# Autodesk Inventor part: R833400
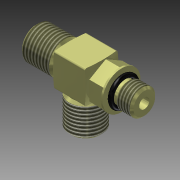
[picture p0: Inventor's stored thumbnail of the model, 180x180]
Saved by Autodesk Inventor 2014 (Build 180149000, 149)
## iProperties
Shininess: 20.0
Length Units: 11272
Angle Units: 11279
Time Units: 11290
Mass Units: 11286
Length Display Precision: 3
Angle Display Precision: 2
Company: Autodesk, Inc.
Created: 2002-06
Part Number: R833400
Material: Steel, Mild A-36
Description: Fitting; TE-C9GC94-S
Document SubType Name: Modeling
Designer: Autodesk, Inc.
Density: 1 g/cm^3
Appearance: Yellow Zinc
Density: 0.0
Volumn: 0.0
Area: 0.0
PropertySet Name: Model Information
Control State: 0
Master: False
Checked Out: False
Last Check In By: JT
Last Check In Date: 2003-06-20
Title: Fitting; TE-C9GC94-S
Author: Autodesk, Inc.
Comments: -
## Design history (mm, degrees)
sketch "Sketch1"
  geometry: L1 (-7.137, -7.137)-(7.137, -7.137); L2 (7.137, -7.137)-(7.137, 7.137); L3 (7.137, 7.137)-(-7.137, 7.137); L4 (-7.137, 7.137)-(-7.137, -7.137); L5 (-7.137, -7.137)-(7.137, 7.137); 2 further points
  constraints: 10 end point, 2 parallel, 1 coincident, 1 horizontal, 1 midpoint, 1 perpendicular
  dimensions: "d3" = 14.2748 distance of L2.end L3.end (= Body_Size); "d4" = 14.2748 distance of L3.end L1.start (= Body_Size)
extrude "Extrusion2" new body sketch "Sketch1" stored distance "d5" = 14.2748 (= Body_Size); taper "d6" = 0 deg
workplane "Work Plane1"
sketch "Sketch2"
  geometry: L1 (-7.137, 10.094)-(-7.137, 0) reference; L2 (7.137, 0)-(7.137, 10.094) reference; L3 (-7.137, 7.137)-(-6.616, 10.094); L4 (7.137, 7.137)-(6.616, 10.094); L5 (7.137, 7.137)-(-7.137, 7.137); L6 (-9.992, 0)-(9.992, 0) reference; L7 (-7.137, 10.094)-(-6.616, 10.094); L8 (6.616, 10.094)-(7.137, 10.094)
  constraints: 10 end point, 2 parallel, 2 point on line, 1 horizontal
  dimensions: "d7" = 14.2748 diameter of L5 L6 (= Body_Size); "d8" = 10 deg angle of L3 L1; "d9" = 10 deg angle of L2 L4 (= d8)
revolve "Revolution1" sketch "Sketch2" stored, may be unused: angle "d10" = 90 deg
fillet "Fillet1" dims "d11" = 0.762
sketch "Sketch3"
  geometry: L1 (-7.137, 7.137)-(-7.137, 0) reference; L2 (-7.137, 0)-(-7.137, -7.137) reference; L3 (0, 0)-(-46.922, 0); L4 (0, 0)-(49.071, 0); L5 (0, 0)-(0, -39.416); L6 (6.708, -7.137)-(-6.708, -7.137) reference; L7 (7.137, 0)-(7.137, 7.137) reference; L8 (7.137, -7.137)-(7.137, 0) reference; L9 (-7.137, 6.134)-(-7.899, 6.134); L10 (-7.899, 6.134)-(-8.909, 7.144); L11 (-8.909, 7.144)-(-20.58, 7.144); L12 (-20.58, 7.144)-(-21.59, 6.134); L13 (-21.59, 6.134)-(-21.59, 5.499); L14 (-21.59, 5.499)-(-20.244, 5.499); L15 (-20.244, 5.499)-(-20.244, 3.086); L16 (-20.244, 3.086)-(-21.59, 3.086); L17 (-21.59, 3.086)-(-21.59, 2.184); L18 (-21.59, 2.184)-(-7.137, 2.184); L19 (7.137, 6.134)-(7.899, 6.134); L20 (7.899, 6.134)-(8.909, 7.144); L21 (8.909, 7.144)-(20.58, 7.144); L22 (20.58, 7.144)-(21.59, 6.134); L23 (21.59, 6.134)-(21.59, 5.499); L24 (21.59, 5.499)-(20.244, 5.499); L25 (20.244, 5.499)-(20.244, 3.086); L26 (20.244, 3.086)-(21.59, 3.086); L27 (21.59, 3.086)-(21.59, 2.184); L28 (21.59, 2.184)-(7.137, 2.184); L29 (-6.134, -7.137)-(-6.134, -7.899); L30 (-6.134, -7.899)-(-7.144, -8.909); L31 (-7.144, -8.909)-(-7.144, -20.58); L32 (-7.144, -20.58)-(-6.134, -21.59); L33 (-6.134, -21.59)-(-5.499, -21.59); L34 (-5.499, -21.59)-(-5.499, -20.244); L35 (-5.499, -20.244)-(-3.086, -20.244); L36 (-3.086, -20.244)-(-3.086, -21.59); L37 (-3.086, -21.59)-(-2.184, -21.59); L38 (-2.184, -21.59)-(-2.184, -7.137); C1 r 0.787 at (-21.031, 4.61); C2 r 0.787 at (-4.61, -21.031); C3 r 0.787 at (21.031, 4.61)
  constraints: 66 end point, 14 perpendicular, 13 parallel, 6 point on line, 5 collinear, 3 centre point, 2 horizontal alignment, 1 vertical alignment
  dimensions: "d12" = 14.2875 diameter of L11 L3 (= Male2_Face_Seal_Thread_OD); "d13" = 12.2682 diameter of L12.end L3 (= Male2_Face_Seal_Lip); "d14" = 45 deg angle of L11 L12; "d15" = 10.9982 diameter of L14 L3 (= Male2_Face_Seal_Groove_Dia); "d16" = 1.3462 distance from line of L15.end L13; "d17" = 4.3688 diameter of L18 L3 (= Male2_Face_Seal_ID); "d18" = 2.413 distance between parallel lines of L16 L14; "d19" = 21.59 distance from line of L13 L3.start (= Male1_M); "d20" = 0.762 distance of L9.start L9.end (= Male2_Face_Seal_Undercut_Length_H); "d21" = 21.59 distance from line of L33 L3.start (= Male1_M); "d22" = 14.2875 diameter of L31 L5 (= Male2_Face_Seal_Thread_OD); "d23" = 45 deg angle of L31 L32; "d24" = 12.2682 diameter of L32.end L5 (= Male2_Face_Seal_Lip); "d25" = 0.762 distance of L29.start L29.end (= Male2_Face_Seal_Undercut_Length_H); "d26" = 10.9982 diameter of L34 L5 (= Male2_Face_Seal_Groove_Dia); "d27" = 2.413 distance between parallel lines of L36 L34; "d28" = 1.3462 distance between parallel lines of L35 L37; "d29" = 4.3688 diameter of L38 L5 (= Male2_Face_Seal_ID); "d30" = 21.59 distance from line of L27 L3.start (= Male2_M); "d31" = 14.2875 diameter of L21 L4 (= Male1_Face_Seal_Thread_OD); "d32" = 10.9982 diameter of L24 L4 (= Male1_Face_Seal_Groove_Dia); "d33" = 2.413 distance between parallel lines of L26 L24; "d34" = 1.3462 distance between parallel lines of L27 L25; "d35" = 0.762 distance of L19.start L19.end (= Male1_Face_Seal_Undercut_Length_H); "d36" = 45 deg angle of L21 L22; "d37" = 12.2682 diameter of L22.end L4 (= Male1_Face_Seal_Lip); "d38" = 4.3688 diameter of L28 L4 (= Male2_Face_Seal_ID); "d48" = 1.5748 diameter of C3 (= Male1_Face_Seal_Seal); "d49" = 1.5748 diameter of C1 (= Male2_Face_Seal_Seal); "d50" = 1.5748 diameter of C2 (= Male2_Face_Seal_Seal); "d53" = 21.0312 horizontal distance of L3.start C1.centre (computed from Male2_M, Male2_Face_Seal_Seal); "d54" = 21.0312 horizontal distance of L3.start C3.centre (computed from Male1_M, Male1_Face_Seal_Seal); "d55" = 21.0312 vertical distance of C2.centre L3.start (computed from Male2_M, Male2_Face_Seal_Seal); "d67" = 7.6454 dimension on C1 L3 (= Male2_Oring_Dia); "d68" = 7.6454 dimension on C3 L4 (= Male1_Oring_Dia); "d69" = 7.6454 dimension on C2 L5 (= Male2_Oring_Dia)
revolve "Male FS1" stored, may be unused: angle "d39" = 90 deg
revolve "Oring FS1" stored, may be unused: angle "d58" = 90 deg
revolve "Male FS2" stored, may be unused: angle "d40" = 90 deg
revolve "Oring FS2" stored, may be unused: angle "d59" = 90 deg
revolve "Male FS3" stored, may be unused: angle "d41" = 90 deg
revolve "Oring FS3" stored, may be unused: angle "d60" = 90 deg
feature "Male Thd FS1" dims "d42" = 25.4, "d43" = 0
feature "Male Thd FS2" dims "d44" = 25.4, "d45" = 0
feature "Male Thd FS3" dims "d46" = 25.4, "d47" = 0
sketch "Sketch4"
  geometry: C1 r 2.184 at (0, 0); 1 further point
  constraints: 1 centre point, 1 coincident
  dimensions: "d73" = 4.3688 diameter of C1 (derived)
extrude "FS1 Hole" cut sketch "Sketch4" distance "d61" = 7.1374 (= 0.5 x Body_Size); taper "d62" = 0 deg
sketch "Sketch5"
  geometry: C1 r 2.184 at (0, 0)
  constraints: 1 centre point
  dimensions: "d71" = 4.3688 diameter of C1 (= Male2_Face_Seal_ID)
extrude "FS2 Hole" cut sketch "Sketch5" distance "d63" = 7.1374 (= 0.5 x Body_Size); taper "d64" = 0 deg
sketch "Sketch6"
  geometry: C1 r 2.184 at (0, 0)
  constraints: 1 centre point
  dimensions: "d72" = 4.3688 diameter of C1 (= Male2_Face_Seal_ID)
extrude "FS3 Hole" cut sketch "Sketch6" distance "d65" = 7.1374 (= 0.5 x Body_Size); taper "d66" = 0 deg
sketch "Sketch13"
  geometry: L1 (0, 0)-(0, -86.34); L2 (6.708, -7.137)-(-6.708, -7.137) reference; L3 (4.648, -7.137)-(4.648, -9.423); L4 (4.648, -9.423)-(5.556, -9.948); L5 (5.556, -9.948)-(5.556, -13.827); L6 (5.556, -13.827)-(4.648, -14.351); L7 (4.648, -14.351)-(4.648, -18.161); L8 (4.648, -18.161)-(5.556, -19.069); L9 (5.556, -19.069)-(5.556, -24.568); L10 (5.556, -24.568)-(4.699, -25.425); L11 (4.699, -25.425)-(0, -25.425); L12 (0, -25.425)-(0, -7.137)
  constraints: 22 end point, 3 perpendicular, 2 collinear, 2 parallel, 2 point on line, 1 midpoint, 1 vertical
  dimensions: "d149" = 45 deg angle of L10 L11; "d150" = 9.2964 diameter of L3 L1 (derived); "d151" = 9.2964 diameter of L7 L1 (derived); "d152" = 11.1125 diameter of L9 L1 (derived); "d153" = 60 deg angle of L6 L7; "d154" = 60 deg angle of L4 L3; "d155" = 2.286 distance from line of L3.end L2 (derived); "d156" = 3.81 distance of L7.end L6.end (derived); "d157" = 9.398 diameter of L10.end L1 (derived); "d158" = 7.2644 vertical distance of L7.end L10.end (derived); "d159" = 18.288 distance between parallel lines of L11 L2 (derived)
revolve "Male OR1" sketch "Sketch13" stored, may be unused: angle "d160" = 90 deg
node "Male OR1 Workplane"
sketch "Sketch14"
  geometry: L1 (0, 8.249)-(7.144, 4.124); L2 (7.144, 4.124)-(7.144, -4.124); L3 (7.144, -4.124)-(0, -8.249); L4 (0, -8.249)-(-7.144, -4.124); L5 (-7.144, -4.124)-(-7.144, 4.124); L6 (-7.144, 4.124)-(0, 8.249); C1 r 5.556 at (0, 0); 2 further points
  constraints: 12 end point, 2 coincident, 1 centre point, 1 vertical alignment, 11 other
  dimensions: "d162" = 14.2875 distance between parallel lines of L6 L3 (derived); "d163" = 11.1125 diameter of C1 (derived)
extrude "Male OR1 Hex Nut" join sketch "Sketch14" distance "d164" = 6.858 (derived); taper "d165" = 0 deg
sketch "Sketch15"
  geometry: C1 r 8.249 at (0, 0); 1 further point
  constraints: 1 centre point, 1 coincident
  dimensions: "d166" = 16.49778 diameter of C1 (derived)
extrude "Male OR1 Washer" join sketch "Sketch15" distance "d167" = 0.79375; taper "d168" = 0 deg
sketch "Sketch16"
  geometry: L1 (0, 0)-(-39.6, 0); C1 r 0.953 at (-16.472, 5.601)
  constraints: 2 end point, 1 centre point, 1 horizontal
  dimensions: "d169" = 16.4719 horizontal distance of C1.centre L1.start (derived); "d170" = 1.905 diameter of C1 (derived); "d172" = 11.2014 diameter of C1.centre L1 (derived)
revolve "Male OR1 Oring" sketch "Sketch16" stored, may be unused: angle "d173" = 90 deg
sketch "Sketch17"
  geometry: C1 r 2.222 at (0, 0); 1 further point
  constraints: 1 centre point, 1 coincident
  dimensions: "d174" = 4.445 diameter of C1 (derived)
extrude "Male OR1 Hole" cut sketch "Sketch17" distance "d175" = 25.4254 (derived); taper "d176" = 0 deg
feature "Male OR1 Thread" dims "d177" = 25.4, "d178" = 0
sketch "Sketch18"
  geometry: L1 (0, 0)-(78.513, 0); L2 (7.137, -7.137)-(7.137, 0) reference; L3 (7.137, 0)-(7.137, 7.137) reference; L4 (7.137, 4.648)-(9.423, 4.648); L5 (9.423, 4.648)-(9.948, 5.556); L6 (9.948, 5.556)-(13.827, 5.556); L7 (13.827, 5.556)-(14.351, 4.648); L8 (14.351, 4.648)-(18.161, 4.648); L9 (18.161, 4.648)-(19.069, 5.556); L10 (19.069, 5.556)-(24.568, 5.556); L11 (24.568, 5.556)-(25.425, 4.699); L12 (25.425, 4.699)-(25.425, 0); L13 (25.425, 0)-(7.137, 0)
  constraints: 22 end point, 6 perpendicular, 2 collinear, 2 point on line, 1 horizontal
  dimensions: "d180" = 45 deg angle of L10 L11; "d181" = 9.2964 diameter of L4 L1 (derived); "d182" = 9.2964 diameter of L8 L1 (derived); "d183" = 60 deg angle of L7 L8; "d184" = 60 deg angle of L4 L5; "d185" = 2.286 distance from line of L4.end L3 (derived); "d186" = 3.81 distance of L8.end L7.end (derived); "d187" = 11.1125 diameter of L10 L1 (derived); "d188" = 9.398 diameter of L11.end L1 (derived); "d189" = 18.288 distance between parallel lines of L12 L3 (derived); "d190" = 7.2644 horizontal distance of L11.end L8.end (derived)
revolve "Male OR2" sketch "Sketch18" stored, may be unused: angle "d191" = 90 deg
node "Male OR2 Workplane"
sketch "Sketch19"
  geometry: L1 (8.249, 0)-(4.124, -7.144); L2 (4.124, -7.144)-(-4.124, -7.144); L3 (-4.124, -7.144)-(-8.249, 0); L4 (-8.249, 0)-(-4.124, 7.144); L5 (-4.124, 7.144)-(4.124, 7.144); L6 (4.124, 7.144)-(8.249, 0); C1 r 5.556 at (0, 0); 2 further points
  constraints: 12 end point, 2 coincident, 1 centre point, 1 horizontal alignment, 11 other
  dimensions: "d193" = 14.2875 distance between parallel lines of L1 L4 (derived); "d194" = 11.1125 diameter of C1 (derived)
extrude "Male OR2 Hex Nut" join sketch "Sketch19" distance "d195" = 6.858 (derived); taper "d196" = 0 deg
sketch "Sketch20"
  geometry: C1 r 8.249 at (0, 0); 1 further point
  constraints: 1 centre point, 1 coincident
  dimensions: "d197" = 16.49778 diameter of C1 (derived)
extrude "Male OR2 Washer" join sketch "Sketch20" distance "d198" = 0.79375; taper "d199" = 0 deg
sketch "Sketch21"
  geometry: L1 (0, 0)-(78.777, 0); C1 r 0.953 at (16.472, 5.601)
  constraints: 2 end point, 1 centre point, 1 horizontal
  dimensions: "d200" = 16.4719 horizontal distance of C1.centre L1.start (derived); "d201" = 11.2014 diameter of C1.centre L1 (derived); "d202" = 1.905 diameter of C1 (derived)
revolve "Male OR2 Oring" sketch "Sketch21" stored, may be unused: angle "d203" = 90 deg
sketch "Sketch22"
  geometry: C1 r 2.222 at (0, 0); 1 further point
  constraints: 1 centre point, 1 coincident
  dimensions: "d204" = 4.445 diameter of C1 (derived)
extrude "Male OR2 Hole" cut sketch "Sketch22" distance "d205" = 25.4254 (derived); taper "d206" = 0 deg
feature "Male OR2 Thread" dims "d207" = 25.4, "d208" = 0
body "Solid1"
other parameters: "Body_Size" = 14.2748 [user parameter; used in 7 equation terms], "Male1_Face_Seal_ID" = 4.3688 [user parameter], "Male1_Face_Seal_Groove_Dia" = 10.9982 [user parameter; used in 1 equation term], "Male1_Face_Seal_Lip" = 12.2682 [user parameter; used in 1 equation term], "Male1_Face_Seal_Thread_OD" = 14.2875 [user parameter; used in 1 equation term], "Male1_Oring_Dia" = 7.6454 [user parameter; used in 1 equation term], "Male1_M" = 21.59 [user parameter; used in 3 equation terms], "Male2_Face_Seal_ID" = 4.3688 [user parameter; used in 5 equation terms], "Male2_Face_Seal_Groove_Dia" = 10.9982 [user parameter; used in 2 equation terms], "Male2_Face_Seal_Lip" = 12.2682 [user parameter; used in 2 equation terms], "Male2_Face_Seal_Thread_OD" = 14.2875 [user parameter; used in 2 equation terms], "Male2_Oring_Dia" = 7.6454 [user parameter; used in 2 equation terms], "Male1_Face_Seal_Undercut_Length_H" = 0.762 [user parameter; used in 1 equation term], "Male2_Face_Seal_Undercut_Length_H" = 0.762 [user parameter; used in 2 equation terms], "Male2_M" = 21.59 [user parameter; used in 3 equation terms], "Male1_Face_Seal_Seal" = 1.5748 [user parameter; used in 2 equation terms], "Male2_Face_Seal_Seal" = 1.5748 [user parameter; used in 4 equation terms], "Oring_Length_I5" = 18.288 [user parameter], "Oring_Lip_V" = 9.398 [user parameter], "Oring_Thread_Length_J3" = 7.2644 [user parameter], "Oring_Thread_OD" = 11.1125 [user parameter], "Oring_Undercut_G" = 9.2964 [user parameter], "Oring_Undercut_G1" = 9.2964 [user parameter], "Oring_Undercut_Width_H" = 2.286 [user parameter], "Oring_Undercut_Width_H1" = 3.81 [user parameter], "Hex_Size_C4" = 14.2875 [user parameter], "Hex_Thk_T1" = 6.858 [user parameter], "Oring_Dia" = 1.905 [user parameter], "TE" = 9.906 [user parameter], "Oring_Hole_ID" = 4.445 [user parameter], "Install_Depth_TE" = 15.5194 [user parameter], "d161" = -15.5194 (derived), "d192" = 15.5194 (derived)
